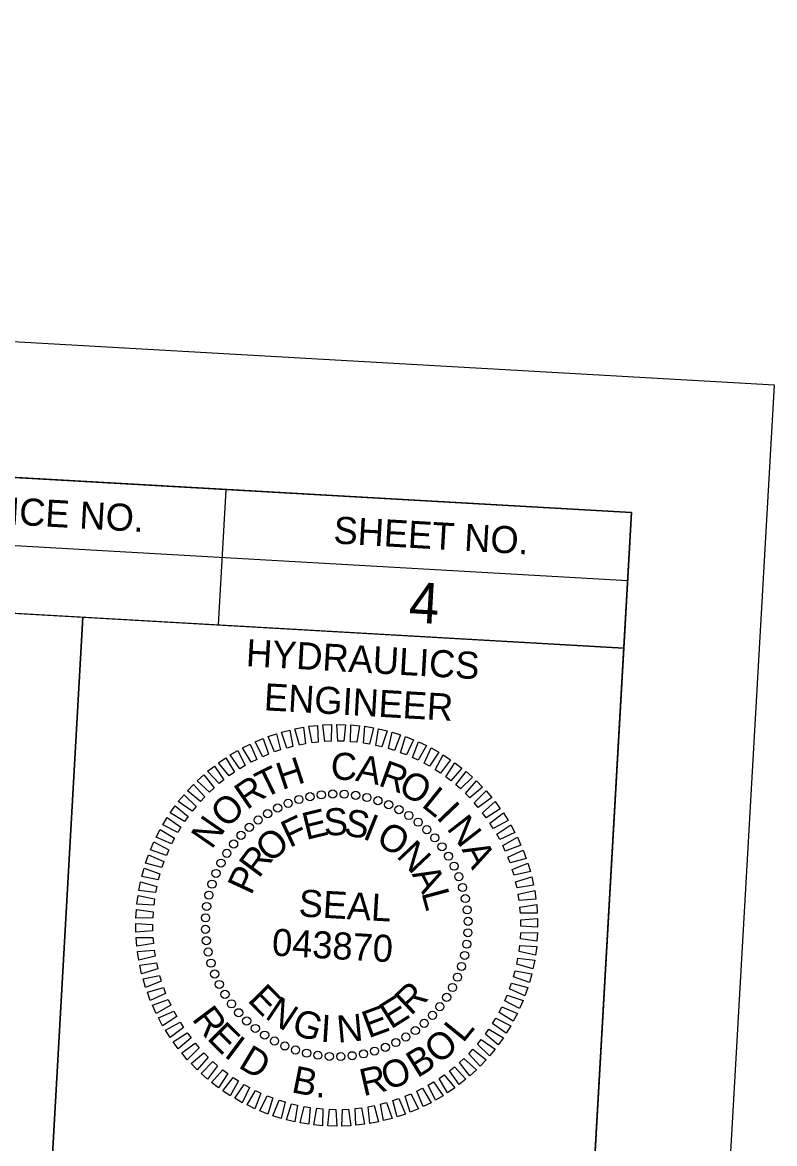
# Model space of a CAD drawing. Extents: x 2602909 to 2604669, y 617940 to 619640.
# Drawn here: x 2604530 to 2604668.9, y 618898.1 to 619105.1 of the extents above; entities that cross this region are included whole.
import ezdxf

# ---------------------------------------------------------------- set-up
doc = ezdxf.new("R2010")
doc.units = 0
for name, color, linetype in [('Default', 7, 'Continuous'), ('Sheet Data Field CELL', 7, 'Continuous'), ('Sheet PE Seal Cell', 7, 'Continuous'), ('Sheet Plan And Profile CELL', 7, 'Continuous'), ('Stewart Plot Border Xerox6279 and LJ5000', 7, 'Continuous')]:
    doc.layers.add(name, color=color, linetype=linetype)

msp = doc.modelspace()

# ---------------------------------------------------------------- linework, layer by layer
at = {"layer": 'Default'}
msp.add_line((2604541.21, 618995.27), (2604534.83, 618882.99), dxfattribs=at)
at = {"layer": 'Sheet PE Seal Cell'}
msp.add_line((2604588.05, 618938.39), (2604588.05, 618938.39), dxfattribs=at)
for points in [[(2604581.16, 618971.68), (2604580.34, 618974.69), (2604581.94, 618974.96), (2604582.28, 618971.9)], [(2604583.49, 618972.08), (2604582.89, 618975.14), (2604584.5, 618975.3), (2604584.63, 618972.22)], [(2604585.86, 618972.31), (2604585.47, 618975.41), (2604587.09, 618975.46), (2604587, 618972.38)], [(2604588.23, 618972.38), (2604588.06, 618975.5), (2604589.67, 618975.44), (2604589.37, 618972.37)], [(2604590.6, 618972.29), (2604590.65, 618975.41), (2604592.25, 618975.23), (2604591.74, 618972.19)], [(2604592.96, 618972.03), (2604593.22, 618975.14), (2604594.81, 618974.85), (2604594.08, 618971.85)], [(2604595.29, 618971.6), (2604595.77, 618974.69), (2604597.34, 618974.29), (2604596.4, 618971.35)], [(2604574.39, 618969.52), (2604572.97, 618972.3), (2604574.47, 618972.89), (2604575.44, 618969.97)], [(2604576.59, 618970.4), (2604575.37, 618973.27), (2604576.91, 618973.76), (2604577.67, 618970.77)], [(2604578.85, 618971.12), (2604577.83, 618974.07), (2604579.4, 618974.45), (2604579.95, 618971.41)], [(2604597.59, 618971.02), (2604598.29, 618974.06), (2604599.82, 618973.55), (2604598.68, 618970.69)], [(2604599.84, 618970.27), (2604600.75, 618973.26), (2604602.24, 618972.65), (2604600.91, 618969.87)], [(2604570.19, 618967.31), (2604568.39, 618969.87), (2604569.8, 618970.67), (2604571.17, 618967.9)], [(2604572.25, 618968.49), (2604570.64, 618971.16), (2604572.09, 618971.86), (2604573.27, 618969.01)], [(2604602.04, 618969.37), (2604603.15, 618972.29), (2604604.6, 618971.57), (2604603.07, 618968.89)], [(2604604.16, 618968.32), (2604605.48, 618971.15), (2604606.87, 618970.34), (2604605.16, 618967.77)], [(2604568.21, 618966), (2604566.25, 618968.42), (2604567.59, 618969.32), (2604569.15, 618966.65)], [(2604606.21, 618967.13), (2604607.72, 618969.86), (2604609.06, 618968.95), (2604607.17, 618966.51)], [(2604566.34, 618964.55), (2604564.2, 618966.83), (2604565.48, 618967.81), (2604567.22, 618965.27)], [(2604608.17, 618965.79), (2604609.87, 618968.41), (2604611.14, 618967.41), (2604609.09, 618965.1)], [(2604610.03, 618964.32), (2604611.91, 618966.81), (2604613.1, 618965.73), (2604610.9, 618963.57)], [(2604562.91, 618961.27), (2604560.48, 618963.23), (2604561.61, 618964.39), (2604563.69, 618962.11)], [(2604564.57, 618962.97), (2604562.28, 618965.09), (2604563.49, 618966.17), (2604565.4, 618963.75)], [(2604611.79, 618962.72), (2604613.83, 618965.08), (2604614.95, 618963.91), (2604612.6, 618961.92)], [(2604561.37, 618959.46), (2604558.81, 618961.25), (2604559.86, 618962.48), (2604562.09, 618960.35)], [(2604613.43, 618961.01), (2604615.63, 618963.22), (2604616.66, 618961.97), (2604614.18, 618960.15)], [(2604559.97, 618957.55), (2604557.29, 618959.15), (2604558.25, 618960.45), (2604560.62, 618958.49)], [(2604614.94, 618959.18), (2604617.3, 618961.23), (2604618.24, 618959.92), (2604615.63, 618958.27)], [(2604558.7, 618955.54), (2604555.92, 618956.96), (2604556.78, 618958.32), (2604559.29, 618956.52)], [(2604616.33, 618957.25), (2604618.82, 618959.14), (2604619.67, 618957.76), (2604616.95, 618956.3)], [(2604557.58, 618953.45), (2604554.7, 618954.67), (2604555.47, 618956.09), (2604558.09, 618954.47)], [(2604617.57, 618955.24), (2604620.19, 618956.94), (2604620.94, 618955.51), (2604618.13, 618954.24)], [(2604618.68, 618953.14), (2604621.4, 618954.65), (2604622.05, 618953.17), (2604619.16, 618952.1)], [(2604556.6, 618951.29), (2604553.65, 618952.3), (2604554.31, 618953.78), (2604557.05, 618952.34)], [(2604619.63, 618950.96), (2604622.46, 618952.29), (2604623, 618950.76), (2604620.04, 618949.9)], [(2604555.78, 618949.07), (2604552.76, 618949.87), (2604553.32, 618951.39), (2604556.15, 618950.15)], [(2604620.43, 618948.73), (2604623.34, 618949.85), (2604623.78, 618948.3), (2604620.77, 618947.64)], [(2604555.11, 618946.79), (2604552.05, 618947.38), (2604552.5, 618948.93), (2604555.41, 618947.89)], [(2604554.61, 618944.47), (2604551.51, 618944.85), (2604551.85, 618946.43), (2604554.82, 618945.59)], [(2604621.07, 618946.45), (2604624.06, 618947.36), (2604624.38, 618945.78), (2604621.33, 618945.33)], [(2604554.26, 618942.12), (2604551.15, 618942.28), (2604551.38, 618943.88), (2604554.4, 618943.26)], [(2604621.55, 618944.12), (2604624.59, 618944.83), (2604624.81, 618943.23), (2604621.74, 618942.99)], [(2604621.87, 618941.77), (2604624.95, 618942.26), (2604625.06, 618940.65), (2604621.97, 618940.63)], [(2604554.09, 618939.76), (2604550.97, 618939.7), (2604551.09, 618941.31), (2604554.14, 618940.9)], [(2604622.03, 618939.4), (2604625.13, 618939.68), (2604625.13, 618938.06), (2604622.05, 618938.26)], [(2604554.07, 618937.39), (2604550.97, 618937.11), (2604550.97, 618938.72), (2604554.05, 618938.53)], [(2604554.23, 618935.02), (2604551.15, 618934.52), (2604551.04, 618936.14), (2604554.13, 618936.16)], [(2604622.01, 618937.03), (2604625.13, 618937.09), (2604625.01, 618935.48), (2604621.96, 618935.89)], [(2604554.54, 618932.67), (2604551.51, 618931.96), (2604551.29, 618933.56), (2604554.36, 618933.79)], [(2604621.84, 618934.67), (2604624.95, 618934.51), (2604624.72, 618932.91), (2604621.7, 618933.53)], [(2604555.03, 618930.34), (2604552.04, 618929.43), (2604551.71, 618931.01), (2604554.77, 618931.46)], [(2604621.49, 618932.32), (2604624.59, 618931.94), (2604624.25, 618930.36), (2604621.28, 618931.2)], [(2604555.67, 618928.06), (2604552.76, 618926.94), (2604552.32, 618928.49), (2604555.33, 618929.15)], [(2604620.99, 618930), (2604624.05, 618929.41), (2604623.6, 618927.86), (2604620.69, 618928.9)], [(2604620.32, 618927.72), (2604623.34, 618926.92), (2604622.78, 618925.4), (2604619.95, 618926.64)], [(2604556.47, 618925.83), (2604553.64, 618924.5), (2604553.1, 618926.02), (2604556.06, 618926.89)], [(2604619.5, 618925.5), (2604622.45, 618924.49), (2604621.79, 618923.01), (2604619.05, 618924.44)], [(2604557.42, 618923.65), (2604554.69, 618922.14), (2604554.04, 618923.62), (2604556.94, 618924.69)], [(2604618.52, 618923.33), (2604621.4, 618922.12), (2604620.63, 618920.7), (2604618.01, 618922.32)], [(2604558.52, 618921.55), (2604555.91, 618919.85), (2604555.16, 618921.28), (2604557.97, 618922.55)], [(2604617.4, 618921.25), (2604620.18, 618919.83), (2604619.32, 618918.47), (2604616.81, 618920.27)], [(2604559.77, 618919.53), (2604557.28, 618917.65), (2604556.43, 618919.03), (2604559.15, 618920.49)], [(2604616.13, 618919.24), (2604618.81, 618917.64), (2604617.85, 618916.33), (2604615.48, 618918.3)], [(2604561.16, 618917.61), (2604558.8, 618915.56), (2604557.86, 618916.87), (2604560.47, 618918.52)], [(2604614.73, 618917.33), (2604617.28, 618915.54), (2604616.24, 618914.31), (2604614.01, 618916.44)], [(2604562.67, 618915.78), (2604560.47, 618913.57), (2604559.44, 618914.82), (2604561.92, 618916.64)], [(2604564.31, 618914.07), (2604562.27, 618911.71), (2604561.15, 618912.88), (2604563.5, 618914.87)], [(2604613.19, 618915.52), (2604615.62, 618913.56), (2604614.49, 618912.4), (2604612.41, 618914.68)], [(2604566.07, 618912.47), (2604564.19, 618909.97), (2604563, 618911.06), (2604565.2, 618913.22)], [(2604611.53, 618913.82), (2604613.82, 618911.7), (2604612.61, 618910.62), (2604610.7, 618913.04)], [(2604567.93, 618911), (2604566.23, 618908.38), (2604564.96, 618909.38), (2604567.01, 618911.69)], [(2604607.89, 618910.79), (2604609.85, 618908.37), (2604608.51, 618907.47), (2604606.95, 618910.13)], [(2604609.76, 618912.24), (2604611.89, 618909.96), (2604610.62, 618908.97), (2604608.88, 618911.52)], [(2604569.89, 618909.66), (2604568.38, 618906.93), (2604567.04, 618907.84), (2604568.93, 618910.28)], [(2604571.94, 618908.47), (2604570.62, 618905.64), (2604569.23, 618906.45), (2604570.94, 618909.02)], [(2604605.91, 618909.48), (2604607.71, 618906.92), (2604606.3, 618906.12), (2604604.93, 618908.88)], [(2604574.06, 618907.41), (2604572.95, 618904.5), (2604571.5, 618905.22), (2604573.03, 618907.9)], [(2604576.26, 618906.51), (2604575.35, 618903.53), (2604573.85, 618904.14), (2604575.19, 618906.92)], [(2604599.51, 618906.39), (2604600.73, 618903.52), (2604599.19, 618903.03), (2604598.43, 618906.02)], [(2604601.71, 618907.27), (2604603.13, 618904.49), (2604601.63, 618903.89), (2604600.66, 618906.82)], [(2604603.85, 618908.3), (2604605.46, 618905.63), (2604604.01, 618904.93), (2604602.83, 618907.78)], [(2604578.51, 618905.77), (2604577.81, 618902.73), (2604576.28, 618903.23), (2604577.42, 618906.1)], [(2604580.81, 618905.18), (2604580.33, 618902.1), (2604578.76, 618902.5), (2604579.7, 618905.44)], [(2604583.14, 618904.76), (2604582.88, 618901.65), (2604581.29, 618901.94), (2604582.01, 618904.94)], [(2604585.5, 618904.5), (2604585.45, 618901.38), (2604583.85, 618901.56), (2604584.36, 618904.6)], [(2604587.87, 618904.4), (2604588.04, 618901.29), (2604586.43, 618901.35), (2604586.73, 618904.42)], [(2604590.24, 618904.47), (2604590.63, 618901.38), (2604589.01, 618901.33), (2604589.1, 618904.41)], [(2604592.6, 618904.71), (2604593.2, 618901.65), (2604591.6, 618901.49), (2604591.47, 618904.57)], [(2604594.94, 618905.11), (2604595.76, 618902.1), (2604594.16, 618901.82), (2604593.82, 618904.89)], [(2604597.25, 618905.67), (2604598.27, 618902.72), (2604596.7, 618902.34), (2604596.15, 618905.37)]]:
    msp.add_lwpolyline(points, close=True, dxfattribs=at)
for centre in [(2604581.06, 618961.62), (2604583.12, 618962.14), (2604585.2, 618962.48), (2604587.31, 618962.63), (2604589.43, 618962.61), (2604591.53, 618962.39), (2604593.61, 618962), (2604577.14, 618960.05), (2604579.07, 618960.92), (2604595.65, 618961.42), (2604597.63, 618960.67), (2604599.53, 618959.75), (2604573.54, 618957.83), (2604575.29, 618959.02), (2604601.35, 618958.67), (2604603.07, 618957.44), (2604571.91, 618956.49), (2604604.67, 618956.05), (2604569.01, 618953.41), (2604570.39, 618955.01), (2604606.14, 618954.54), (2604567.77, 618951.69), (2604607.48, 618952.9), (2604608.67, 618951.15), (2604566.69, 618949.88), (2604609.71, 618949.31), (2604565.77, 618947.97), (2604610.57, 618947.38), (2604565.02, 618945.99), (2604611.27, 618945.38), (2604564.45, 618943.96), (2604611.79, 618943.33), (2604564.05, 618941.88), (2604612.13, 618941.24), (2604563.84, 618939.77), (2604612.29, 618939.13), (2604563.81, 618937.66), (2604612.26, 618937.02), (2604563.97, 618935.55), (2604612.05, 618934.91), (2604564.31, 618933.46), (2604611.65, 618932.83), (2604564.83, 618931.41), (2604611.08, 618930.8), (2604565.52, 618929.41), (2604610.33, 618928.82), (2604566.39, 618927.48), (2604609.41, 618926.91), (2604567.43, 618925.64), (2604608.33, 618925.09), (2604568.62, 618923.89), (2604569.95, 618922.25), (2604607.09, 618923.38), (2604571.43, 618920.73), (2604604.19, 618920.3), (2604605.71, 618921.78), (2604573.03, 618919.35), (2604574.75, 618918.12), (2604602.56, 618918.96), (2604576.57, 618917.03), (2604578.47, 618916.12), (2604598.96, 618916.74), (2604600.81, 618917.77), (2604580.45, 618915.37), (2604582.49, 618914.79), (2604584.57, 618914.4), (2604586.67, 618914.18), (2604588.79, 618914.16), (2604590.9, 618914.31), (2604592.98, 618914.65), (2604595.03, 618915.17), (2604597.03, 618915.87)]:
    msp.add_circle(centre, 0.75, dxfattribs=at)
at = {"layer": 'Sheet Plan And Profile CELL'}
for p, q in [((2604567.6, 619018.81), (2604566.17, 618993.85)), ((2604442.04, 619013.44), (2604641.76, 619002.06))]:
    msp.add_line(p, q, dxfattribs=at)
for points in [[(2604642.48, 619014.59), (2603144.9, 619099.88), (2603085.2, 618051.58), (2604582.77, 617966.29)], [(2604442.75, 619025.97), (2604642.48, 619014.59), (2604641.05, 618989.58), (2604441.33, 619000.96)], [(2604441.33, 619000.96), (2604541.21, 618995.27), (2604534.82, 618882.94), (2604434.94, 618888.65)], [(2604541.21, 618995.27), (2604641.04, 618989.59), (2604634.66, 618877.26), (2604534.82, 618882.94)]]:
    msp.add_lwpolyline(points, close=True, dxfattribs=at)
at = {"layer": 'Stewart Plot Border Xerox6279 and LJ5000'}
msp.add_lwpolyline([(2602909.06, 618036.57), (2604606.31, 617939.91), (2604668.86, 619038.13), (2602971.61, 619134.8)], close=True, dxfattribs=at)

# ---------------------------------------------------------------- texts
at = {"layer": 'Default'}
for s, p in [('HYDRAULICS', (2604571.21, 618986.27)), ('ENGINEER', (2604574.52, 618978.11))]:
    msp.add_text(s, height=5, rotation=356.7403, dxfattribs=at).set_placement(p)
at = {"layer": 'Sheet Data Field CELL'}
msp.add_text('4', height=7.5, rotation=356.7403, dxfattribs=at).set_placement((2604601.22, 618994.35))
at = {"layer": 'Sheet PE Seal Cell'}
for s, rotation, p in [('H', 18.3413, (2604577.93, 618963.35)), ('C', 358.7021, (2604586.91, 618965.3)), ('A', 349.197, (2604591.37, 618965.12)), ('R', 340.1496, (2604595.53, 618964.27)), ('T', 26.1305, (2604574.64, 618961.75)), ('O', 331.9409, (2604599.15, 618962.93)), ('R', 34.3392, (2604571.44, 618959.6)), ('O', 45.0643, (2604567.79, 618956.14)), ('L', 321.2157, (2604603.52, 618960.44)), ('I', 313.7506, (2604606.25, 618958.24)), ('N', 55.2748, (2604564.96, 618952.27)), ('F', 25.4042, (2604579.34, 618952.66)), ('E', 13.7262, (2604582.4, 618954.13)), ('S', 1.964, (2604585.73, 618954.95)), ('S', 350.005, (2604589.21, 618955.07)), ('I', 338.0461, (2604592.64, 618954.47)), ('N', 307.8106, (2604608.21, 618956.25)), ('O', 329.2906, (2604595.04, 618953.58)), ('O', 41.2129, (2604575.78, 618949.75)), ('N', 313.4818, (2604598.91, 618951.1)), ('R', 53.3124, (2604573.67, 618946.92)), ('A', 297.6002, (2604611.06, 618952.4)), ('P', 65.0746, (2604572.24, 618943.81)), ('A', 298.4318, (2604601.84, 618947.85)), ('SEAL', 356.7403, (2604580.93, 618940.05)), ('L', 285.0959, (2604603.65, 618944.41)), ('043870', 356.7403, (2604576, 618932.82)), ('E', 314.5909, (2604571.42, 618924.46)), ('R', 43.7832, (2604601.75, 618921.57)), ('N', 326.3531, (2604574.61, 618921.36)), ('E', 32.021, (2604598.03, 618919.13)), ('R', 306.9028, (2604561.19, 618921.08)), ('E', 20.2587, (2604593.9, 618917.5)), ('G', 341.4032, (2604579.49, 618918.46)), ('I', 356.4532, (2604584.97, 618916.92)), ('N', 5.2087, (2604588.27, 618916.7)), ('E', 315.1115, (2604563.94, 618917.42)), ('O', 40.1911, (2604606.88, 618912.57)), ('L', 50.9163, (2604611.35, 618916.53)), ('I', 323.0913, (2604567.08, 618914.28)), ('D', 329.0313, (2604569.69, 618912.24)), ('B', 31.849, (2604602.93, 618910.11)), ('O', 21.1238, (2604597.41, 618907.84)), ('B', 348.6038, (2604579.51, 618907.6)), ('R', 12.9152, (2604592.95, 618906.82)), ('.', 356.9459, (2604584.07, 618906.69))]:
    msp.add_text(s, height=5, rotation=rotation, dxfattribs=at).set_placement(p)
at = {"layer": 'Sheet Plan And Profile CELL'}
for s, height, p in [('PROJECT REFERENCE NO.', 5.0001, (2604464.42, 619016.02)), ('SHEET NO.', 5, (2604587.36, 619008.92))]:
    msp.add_text(s, height=height, rotation=356.7403, dxfattribs=at).set_placement(p)

doc.saveas('drawing.dxf')
